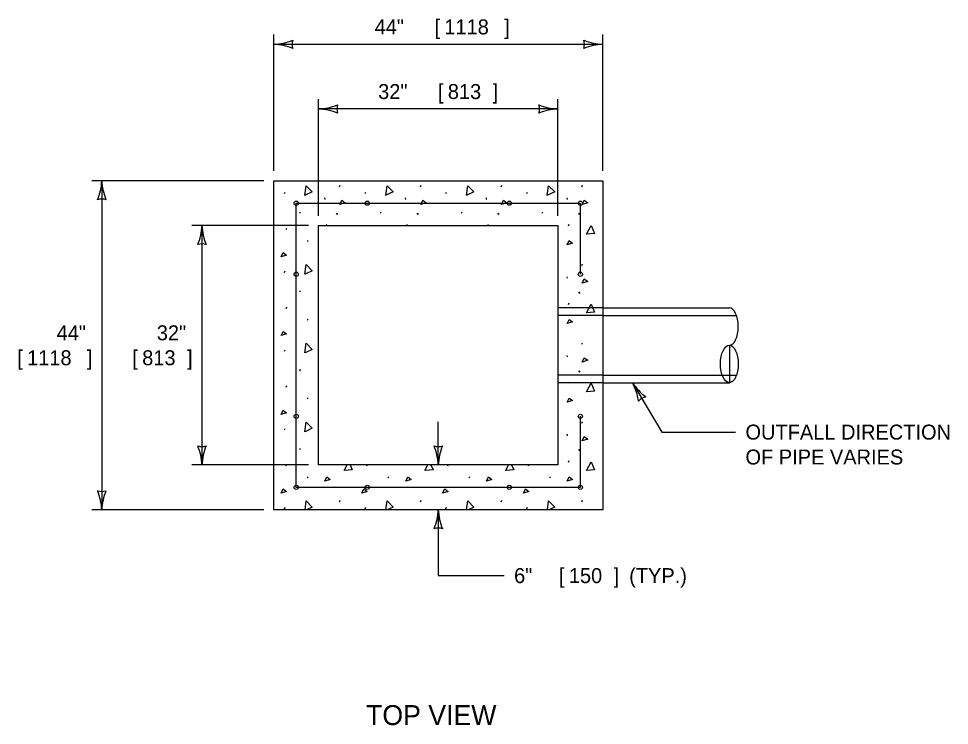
# Model space of a CAD drawing. Extents: x 49991.4 to 50041.6, y 49987.6 to 50011.4.
# Drawn here: x 50037.869 to 50041.603, y 49995.669 to 49998.505 of the extents above; entities that cross this region are included whole.
import ezdxf

# ---------------------------------------------------------------- set-up
doc = ezdxf.new("R2010")
doc.units = 0
for name, color, linetype in [('Level 1', 7, 'Continuous'), ('Level 2', 7, 'Continuous'), ('Level 3', 7, 'Continuous'), ('Level 4', 7, 'Continuous')]:
    doc.layers.add(name, color=color, linetype=linetype)

msp = doc.modelspace()

# ---------------------------------------------------------------- linework, layer by layer
at = {"layer": 'Level 1'}
for p, q in [((50040.2125, 49997.3444), (50040.7204, 49997.3444)), ((50040.2125, 49997.3144), (50040.749, 49997.3144)), ((50040.7204, 49997.1944), (50040.7204, 49997.0444)), ((50040.2125, 49997.0744), (50040.749, 49997.0744)), ((50040.2125, 49997.0444), (50040.7204, 49997.0444))]:
    msp.add_line(p, q, dxfattribs=at)
for points in [[(50038.8925, 49997.8544), (50040.2125, 49997.8544), (50040.2125, 49996.5344), (50038.8925, 49996.5344)], [(50039.0725, 49997.6744), (50040.0325, 49997.6744), (50040.0325, 49996.7144), (50039.0725, 49996.7144)]]:
    msp.add_lwpolyline(points, close=True, dxfattribs=at)
msp.add_lwpolyline([(50040.1225, 49996.9094), (50040.1225, 49996.6244), (50038.9825, 49996.6244), (50038.9825, 49997.7644), (50040.1225, 49997.7644), (50040.1225, 49997.4794)], dxfattribs=at)
for centre in [(50038.9825, 49997.7644), (50038.9825, 49997.7644), (50039.2675, 49997.7644), (50039.8375, 49997.7644), (50040.1225, 49997.7644), (50040.1225, 49997.7644), (50040.1225, 49997.7644), (50040.1225, 49997.7644), (50038.9825, 49997.4794), (50040.1225, 49997.4794), (50038.9825, 49996.9094), (50040.1225, 49996.9094), (50038.9825, 49996.6244), (50038.9825, 49996.6244), (50039.2675, 49996.6244), (50039.8375, 49996.6244), (50040.1225, 49996.6244), (50040.1225, 49996.6244)]:
    msp.add_circle(centre, 0.0084, dxfattribs=at)
msp.add_ellipse((50040.7204, 49997.2694), major_axis=(0, 0.075), ratio=0.477867, start_param=3.141593, end_param=6.283185, dxfattribs=at)
msp.add_ellipse((50040.7204, 49997.1194), major_axis=(0, 0.075), ratio=0.477867, dxfattribs=at)
msp.add_ellipse((50040.7204, 49997.1194), major_axis=(0, 0.075), ratio=0.477867, dxfattribs=at)
at = {"layer": 'Level 3'}
for p, q in [((50038.8925, 49997.8944), (50038.8925, 49998.4419)), ((50040.2125, 49997.8944), (50040.2125, 49998.4419)), ((50038.8925, 49998.4019), (50040.2125, 49998.4019)), ((50039.0725, 49997.7144), (50039.0725, 49998.1825)), ((50040.0325, 49997.7144), (50040.0325, 49998.1825)), ((50040.0325, 49998.1425), (50039.0725, 49998.1425)), ((50038.8525, 49997.8544), (50038.1626, 49997.8544)), ((50038.2026, 49997.8544), (50038.2026, 49996.5344)), ((50039.0325, 49997.6744), (50038.5644, 49997.6744)), ((50038.6044, 49997.6744), (50038.6044, 49996.7144)), ((50040.3318, 49997.0444), (50040.4494, 49996.8461)), ((50039.5525, 49996.7144), (50039.5525, 49996.8878)), ((50040.4494, 49996.8461), (50040.7451, 49996.8461)), ((50039.0325, 49996.7144), (50038.5644, 49996.7144)), ((50038.8525, 49996.5344), (50038.1626, 49996.5344))]:
    msp.add_line(p, q, dxfattribs=at)
msp.add_lwpolyline([(50039.5525, 49996.5344), (50039.5525, 49996.2702), (50039.8167, 49996.2702)], dxfattribs=at)
for centre, radius, start, end in [((50038.881, 49998.6346), 0.233, 272.8273, 292.0772), ((50038.881, 49998.6346), 0.233, 272.8273, 292.0772), ((50038.8834, 49998.1798), 0.2223, 67.456, 87.6395), ((50038.8834, 49998.1798), 0.2223, 67.456, 87.6395), ((50039.0207, 49998.4019), 0.0548, 162.1388, 197.8612), ((50039.0207, 49998.4019), 0.0548, 162.1388, 197.8612), ((50040.2217, 49998.624), 0.2223, 247.456, 267.6395), ((50040.0843, 49998.4019), 0.0548, 342.1388, 17.8612), ((50040.224, 49998.1692), 0.233, 92.8273, 112.0772), ((50039.061, 49998.3752), 0.233, 272.8273, 292.0772), ((50039.061, 49998.3752), 0.233, 272.8273, 292.0772), ((50039.0634, 49997.9203), 0.2223, 67.456, 87.6395), ((50039.0634, 49997.9203), 0.2223, 67.456, 87.6395), ((50039.2007, 49998.1425), 0.0548, 162.1388, 197.8612), ((50039.2007, 49998.1425), 0.0548, 162.1388, 197.8612), ((50040.0417, 49998.3646), 0.2223, 247.456, 267.6395), ((50039.9043, 49998.1425), 0.0548, 342.1388, 17.8612), ((50040.0417, 49998.3646), 0.2223, 247.456, 267.6395), ((50039.9043, 49998.1425), 0.0548, 342.1388, 17.8612), ((50040.044, 49997.9098), 0.233, 92.8273, 112.0772), ((50040.044, 49997.9098), 0.233, 92.8273, 112.0772), ((50037.9805, 49997.8635), 0.2223, 337.456, 357.6395), ((50038.4353, 49997.8659), 0.233, 182.8273, 202.0772), ((50038.2026, 49997.7261), 0.0548, 72.1388, 107.8612), ((50038.3823, 49997.6835), 0.2223, 337.456, 357.6395), ((50038.3823, 49997.6835), 0.2223, 337.456, 357.6395), ((50038.8371, 49997.6859), 0.233, 182.8273, 202.0772), ((50038.8371, 49997.6859), 0.233, 182.8273, 202.0772), ((50038.6044, 49997.5461), 0.0548, 72.1388, 107.8612), ((50038.6044, 49997.5461), 0.0548, 72.1388, 107.8612), ((50040.136, 49996.9389), 0.2223, 8.1365, 28.32), ((50040.526, 49997.173), 0.233, 213.5078, 232.7577), ((50040.3972, 49996.9341), 0.0548, 102.8193, 138.5417), ((50038.6044, 49996.8426), 0.0548, 252.1388, 287.8612), ((50038.3717, 49996.7029), 0.233, 2.8273, 22.0772), ((50038.6044, 49996.8426), 0.0548, 252.1388, 287.8612), ((50038.3717, 49996.7029), 0.233, 2.8273, 22.0772), ((50038.8266, 49996.7052), 0.2223, 157.456, 177.6395), ((50038.8266, 49996.7052), 0.2223, 157.456, 177.6395), ((50039.5525, 49996.8426), 0.0548, 252.1388, 287.8612), ((50039.3198, 49996.7029), 0.233, 2.8273, 22.0772), ((50039.5525, 49996.8426), 0.0548, 252.1388, 287.8612), ((50039.3198, 49996.7029), 0.233, 2.8273, 22.0772), ((50039.7747, 49996.7052), 0.2223, 157.456, 177.6395), ((50039.7747, 49996.7052), 0.2223, 157.456, 177.6395), ((50038.2026, 49996.6626), 0.0548, 252.1388, 287.8612), ((50037.9699, 49996.5229), 0.233, 2.8273, 22.0772), ((50038.2026, 49996.6626), 0.0548, 252.1388, 287.8612), ((50037.9699, 49996.5229), 0.233, 2.8273, 22.0772), ((50038.4247, 49996.5252), 0.2223, 157.456, 177.6395), ((50038.4247, 49996.5252), 0.2223, 157.456, 177.6395), ((50039.3304, 49996.5435), 0.2223, 337.456, 357.6395), ((50039.3304, 49996.5435), 0.2223, 337.456, 357.6395), ((50039.7852, 49996.5459), 0.233, 182.8273, 202.0772), ((50039.7852, 49996.5459), 0.233, 182.8273, 202.0772), ((50039.5525, 49996.4061), 0.0548, 72.1388, 107.8612), ((50039.5525, 49996.4061), 0.0548, 72.1388, 107.8612)]:
    msp.add_arc(centre, radius, start, end, dxfattribs=at)
at = {"layer": 'Level 4'}
for p, q in [((50039.1565, 49997.8306), (50039.1592, 49997.8367)), ((50039.4807, 49997.8306), (50039.4834, 49997.8367)), ((50039.8048, 49997.8306), (50039.8075, 49997.8367)), ((50040.129, 49997.8306), (50040.1317, 49997.8367)), ((50038.9353, 49997.8028), (50038.938, 49997.8089)), ((50039.2594, 49997.8028), (50039.2621, 49997.8089)), ((50039.5835, 49997.8028), (50039.5862, 49997.8089)), ((50039.9077, 49997.8028), (50039.9104, 49997.8089)), ((50039.0961, 49997.7858), (50039.0968, 49997.7797)), ((50039.4203, 49997.7858), (50039.421, 49997.7797)), ((50039.7444, 49997.7858), (50039.7451, 49997.7797)), ((50040.0685, 49997.7858), (50040.0692, 49997.7797)), ((50038.9968, 49997.7243), (50038.9995, 49997.7304)), ((50039.1423, 49997.7243), (50039.145, 49997.7203)), ((50039.145, 49997.7228), (50039.1477, 49997.7187)), ((50039.321, 49997.7243), (50039.3237, 49997.7304)), ((50039.4665, 49997.7243), (50039.4692, 49997.7203)), ((50039.4692, 49997.7228), (50039.4719, 49997.7187)), ((50039.6451, 49997.7243), (50039.6478, 49997.7304)), ((50039.7906, 49997.7243), (50039.7933, 49997.7203)), ((50039.7933, 49997.7228), (50039.796, 49997.7187)), ((50039.9692, 49997.7243), (50039.972, 49997.7304)), ((50040.1147, 49997.7243), (50040.1174, 49997.7203)), ((50040.1174, 49997.7228), (50040.1202, 49997.7187)), ((50038.942, 49997.6586), (50038.9447, 49997.6647)), ((50039.1025, 49997.6744), (50039.1051, 49997.6803)), ((50039.4266, 49997.6744), (50039.4292, 49997.6803)), ((50039.7508, 49997.6744), (50039.7534, 49997.6803)), ((50040.0748, 49997.6742), (50040.0775, 49997.6803)), ((50039.0266, 49997.6153), (50039.0293, 49997.6112)), ((50040.129, 49997.5145), (50040.1317, 49997.5206)), ((50038.9353, 49997.4867), (50038.938, 49997.4928)), ((50040.0685, 49997.4697), (50040.0692, 49997.4637)), ((50038.9968, 49997.4082), (50038.9995, 49997.4143)), ((50040.1147, 49997.4082), (50040.1174, 49997.4042)), ((50040.1174, 49997.4067), (50040.1202, 49997.4026)), ((50038.942, 49997.3425), (50038.9447, 49997.3486)), ((50040.0748, 49997.3581), (50040.0775, 49997.3642)), ((50040.2125, 49997.3444), (50040.0325, 49997.3444)), ((50040.2125, 49997.3144), (50040.0325, 49997.3144)), ((50039.0266, 49997.2992), (50039.0293, 49997.2952)), ((50040.129, 49997.1984), (50040.1317, 49997.2045)), ((50038.9353, 49997.1707), (50038.938, 49997.1767)), ((50040.0685, 49997.1537), (50040.0692, 49997.1476)), ((50038.9968, 49997.0922), (50038.9995, 49997.0983)), ((50040.1147, 49997.0922), (50040.1174, 49997.0881)), ((50040.1174, 49997.0906), (50040.1202, 49997.0866)), ((50040.2125, 49997.0744), (50040.0325, 49997.0744)), ((50040.0748, 49997.042), (50040.0775, 49997.0481)), ((50038.942, 49997.0264), (50038.9447, 49997.0325)), ((50040.2125, 49997.0444), (50040.0325, 49997.0444)), ((50039.0266, 49996.9831), (50039.0293, 49996.9791)), ((50038.9353, 49996.8546), (50038.938, 49996.8607)), ((50040.129, 49996.8823), (50040.1317, 49996.8884)), ((50040.0685, 49996.8376), (50040.0692, 49996.8315)), ((50038.9968, 49996.7761), (50038.9995, 49996.7822)), ((50040.1147, 49996.7761), (50040.1174, 49996.772)), ((50040.1174, 49996.7745), (50040.1202, 49996.7705)), ((50038.942, 49996.7104), (50038.9447, 49996.7164)), ((50039.2662, 49996.7104), (50039.2679, 49996.7144)), ((50039.5903, 49996.7104), (50039.5921, 49996.7144)), ((50039.9144, 49996.7104), (50039.9162, 49996.7144)), ((50040.0748, 49996.7259), (50040.0775, 49996.732)), ((50039.0266, 49996.667), (50039.0293, 49996.663)), ((50039.3507, 49996.667), (50039.3535, 49996.663)), ((50039.6749, 49996.667), (50039.6776, 49996.663)), ((50039.999, 49996.667), (50040.0017, 49996.663)), ((50039.1565, 49996.5662), (50039.1592, 49996.5723)), ((50039.4807, 49996.5662), (50039.4834, 49996.5723)), ((50039.8048, 49996.5662), (50039.8075, 49996.5723)), ((50040.129, 49996.5662), (50040.1317, 49996.5723)), ((50038.9353, 49996.5385), (50038.938, 49996.5446)), ((50039.2594, 49996.5385), (50039.2621, 49996.5446)), ((50039.5835, 49996.5385), (50039.5862, 49996.5446)), ((50039.9077, 49996.5385), (50039.9104, 49996.5446))]:
    msp.add_line(p, q, dxfattribs=at)
for points in [[(50039.0176, 49997.7958), (50039.0229, 49997.8345), (50039.0472, 49997.8095), (50039.0182, 49997.7961)], [(50039.3417, 49997.7958), (50039.3471, 49997.8345), (50039.3713, 49997.8095), (50039.3424, 49997.7961)], [(50039.6659, 49997.7958), (50039.6712, 49997.8345), (50039.6955, 49997.8095), (50039.6665, 49997.7961)], [(50039.99, 49997.7958), (50039.9954, 49997.8345), (50040.0196, 49997.8095), (50039.9906, 49997.7961)], [(50039.1579, 49997.7595), (50039.166, 49997.7764), (50039.1795, 49997.7663), (50039.1579, 49997.7595)], [(50039.482, 49997.7595), (50039.4902, 49997.7764), (50039.5037, 49997.7663), (50039.482, 49997.7595)], [(50039.8062, 49997.7595), (50039.8143, 49997.7764), (50039.8278, 49997.7663), (50039.8062, 49997.7595)], [(50040.1303, 49997.7595), (50040.1384, 49997.7764), (50040.152, 49997.7663), (50040.1303, 49997.7595)], [(50039.1928, 49997.6744), (50039.1931, 49997.6749), (50039.1933, 49997.6744)], [(50039.517, 49997.6744), (50039.5172, 49997.6749), (50039.5174, 49997.6744)], [(50039.8411, 49997.6744), (50039.8414, 49997.6749), (50039.8416, 49997.6744)], [(50040.1472, 49997.6403), (50040.1655, 49997.6749), (50040.1797, 49997.6431), (50040.1479, 49997.6403)], [(50040.0701, 49997.5977), (50040.0782, 49997.6146), (50040.0917, 49997.6045), (50040.0701, 49997.5977)], [(50038.9219, 49997.5493), (50038.93, 49997.5663), (50038.9435, 49997.5561), (50038.9219, 49997.5493)], [(50039.0176, 49997.4797), (50039.0229, 49997.5184), (50039.0472, 49997.4934), (50039.0182, 49997.48)], [(50040.1303, 49997.4434), (50040.1384, 49997.4604), (50040.152, 49997.4502), (50040.1303, 49997.4434)], [(50040.1472, 49997.3243), (50040.1655, 49997.3588), (50040.1797, 49997.327), (50040.1479, 49997.3243)], [(50040.0701, 49997.2816), (50040.0782, 49997.2985), (50040.0917, 49997.2884), (50040.0701, 49997.2816)], [(50038.9219, 49997.2333), (50038.93, 49997.2502), (50038.9435, 49997.24), (50038.9219, 49997.2333)], [(50039.0176, 49997.1637), (50039.0229, 49997.2023), (50039.0472, 49997.1773), (50039.0182, 49997.1639)], [(50040.1303, 49997.1273), (50040.1384, 49997.1443), (50040.152, 49997.1341), (50040.1303, 49997.1273)], [(50040.1472, 49997.0082), (50040.1655, 49997.0427), (50040.1797, 49997.0109), (50040.1479, 49997.0082)], [(50040.0701, 49996.9655), (50040.0782, 49996.9825), (50040.0917, 49996.9723), (50040.0701, 49996.9655)], [(50038.9219, 49996.9172), (50038.93, 49996.9341), (50038.9435, 49996.9239), (50038.9219, 49996.9172)], [(50039.0176, 49996.8476), (50039.0229, 49996.8862), (50039.0472, 49996.8612), (50039.0182, 49996.8478)], [(50040.1303, 49996.8113), (50040.1384, 49996.8282), (50040.152, 49996.818), (50040.1303, 49996.8113)], [(50039.1748, 49996.6921), (50039.1866, 49996.7144)], [(50039.1985, 49996.7144), (50039.2073, 49996.6948), (50039.1755, 49996.6921)], [(50039.499, 49996.6921), (50039.5107, 49996.7144)], [(50039.5227, 49996.7144), (50039.5314, 49996.6948), (50039.4996, 49996.6921)], [(50039.8231, 49996.6921), (50039.8349, 49996.7144)], [(50039.8468, 49996.7144), (50039.8556, 49996.6948), (50039.8238, 49996.6921)], [(50040.1472, 49996.6921), (50040.1655, 49996.7266), (50040.1797, 49996.6948), (50040.1479, 49996.6921)], [(50039.0977, 49996.6495), (50039.1058, 49996.6664), (50039.1193, 49996.6562), (50039.0977, 49996.6495)], [(50039.4218, 49996.6495), (50039.4299, 49996.6664), (50039.4434, 49996.6562), (50039.4218, 49996.6495)], [(50039.7459, 49996.6495), (50039.7541, 49996.6664), (50039.7676, 49996.6562), (50039.7459, 49996.6495)], [(50040.0701, 49996.6495), (50040.0782, 49996.6664), (50040.0917, 49996.6562), (50040.0701, 49996.6495)], [(50038.9219, 49996.6011), (50038.93, 49996.618), (50038.9435, 49996.6078), (50038.9219, 49996.6011)], [(50039.246, 49996.6011), (50039.2541, 49996.618), (50039.2676, 49996.6078), (50039.246, 49996.6011)], [(50039.5701, 49996.6011), (50039.5783, 49996.618), (50039.5918, 49996.6078), (50039.5701, 49996.6011)], [(50039.8943, 49996.6011), (50039.9024, 49996.618), (50039.9159, 49996.6078), (50039.8943, 49996.6011)], [(50039.018, 49996.5344), (50039.0229, 49996.5702), (50039.0472, 49996.5451), (50039.0239, 49996.5344)], [(50039.3421, 49996.5344), (50039.3471, 49996.5702), (50039.3713, 49996.5451), (50039.3481, 49996.5344)], [(50039.6663, 49996.5344), (50039.6712, 49996.5702), (50039.6955, 49996.5451), (50039.6722, 49996.5344)], [(50039.9904, 49996.5344), (50039.9954, 49996.5702), (50040.0196, 49996.5451), (50039.9964, 49996.5344)]]:
    msp.add_lwpolyline(points, dxfattribs=at)

# ---------------------------------------------------------------- texts
at = {"layer": 'Level 2'}
for s, height, p in [('[', 0.06, (50039.5372, 49998.4419)), (']', 0.06, (50039.8169, 49998.4419)), ('44" ', 0.06, (50039.2972, 49998.4419)), ('1118', 0.06, (50039.5769, 49998.4419)), ('32" ', 0.06, (50039.3113, 49998.1825)), ('[', 0.06, (50039.5513, 49998.1825)), ('813', 0.06, (50039.5909, 49998.1825)), (']', 0.06, (50039.7709, 49998.1825)), ('44"', 0.06, (50038.0213, 49997.2144)), ('32"', 0.06, (50038.4232, 49997.2144)), ('[', 0.06, (50037.8631, 49997.1144)), ('1118', 0.06, (50037.9028, 49997.1144)), (']', 0.06, (50038.1428, 49997.1144)), ('[', 0.06, (50038.3249, 49997.1144)), ('813', 0.06, (50038.3646, 49997.1144)), (']', 0.06, (50038.5446, 49997.1144)), ('OUTFALL DIRECTION', 0.06, (50040.7851, 49996.8161)), ('OF PIPE VARIES', 0.06, (50040.7851, 49996.7161)), ('6" ', 0.06, (50039.8567, 49996.2402)), ('[', 0.06, (50040.0367, 49996.2402)), ('150', 0.06, (50040.0764, 49996.2402)), (']', 0.06, (50040.2564, 49996.2402)), (' (TYP.)', 0.06, (50040.2961, 49996.2402)), ('TOP VIEW', 0.08, (50039.2629, 49995.6705))]:
    msp.add_text(s, height=height, dxfattribs=at).set_placement(p)

doc.saveas('drawing.dxf')
